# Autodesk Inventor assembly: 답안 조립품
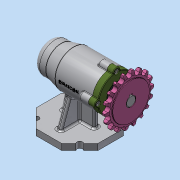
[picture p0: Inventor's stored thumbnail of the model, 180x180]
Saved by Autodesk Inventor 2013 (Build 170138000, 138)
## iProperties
Created: 2021-01
Part Number: 답안 조립품
Document SubType Name: Assembly
Designer: Administrator
Author: Administrator
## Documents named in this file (12)
- C:\Users\Administrator\Desktop\710106V1029\답안 조립품.iam
- C:\Users\Administrator\Desktop\710106V1029\본체1.ipt
- C:\Users\Administrator\Desktop\710106V1029\베어링 51202.ipt
- C:\Users\Administrator\Desktop\710106V1029\볼트 M4.ipt
- C:\Users\Administrator\Desktop\710106V1029\어댑터슬리브.ipt
- C:\Users\Administrator\Desktop\710106V1029\커버.ipt
- C:\Users\Administrator\Desktop\710106V1029\베어링 6004.ipt
- C:\Users\Administrator\Desktop\710106V1029\오일 실.ipt
- C:\Users\Administrator\Desktop\710106V1029\멈춤나사 M3.ipt
- C:\Users\Administrator\Desktop\710106V1029\스프로킷.ipt
- C:\Users\Administrator\Desktop\710106V1029\축.ipt
- C:\Users\Administrator\Desktop\710106V1029\키 5 x 5 x 14.ipt
